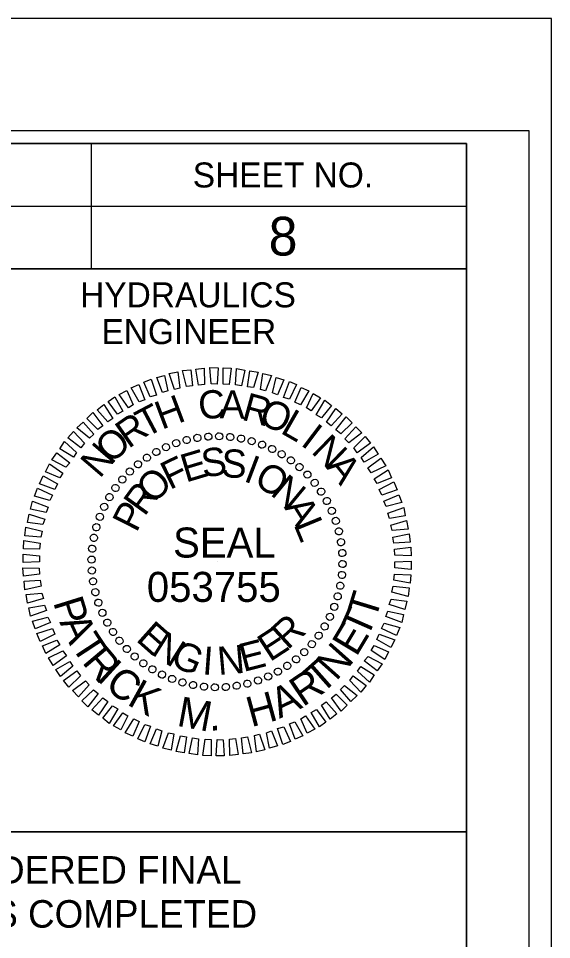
# Model space of a CAD drawing. Extents: x 1629887 to 1632095, y 1174261 to 1175361.
# Drawn here: x 1631464.8 to 1631571.3, y 1175176.7 to 1175360.8 of the extents above; entities that cross this region are included whole.
import ezdxf

# ---------------------------------------------------------------- set-up
doc = ezdxf.new("R2010")
doc.units = 0
for name, color, linetype in [('Sheet Data Field CELL', 7, 'Continuous'), ('Sheet PE Seal Cell', 7, 'Continuous'), ('Sheet Plot Border Inside CELL', 7, 'Continuous'), ('Sheet Plot Border Outside CELL', 7, 'Continuous'), ('Sheet Profile CELL', 7, 'Continuous'), ('Sheet Profile Grid Major CELL', 7, 'Continuous'), ('Sheet Sticker Exception Certification CELL', 7, 'Continuous')]:
    doc.layers.add(name, color=color, linetype=linetype)

msp = doc.modelspace()

# ---------------------------------------------------------------- linework, layer by layer
at = {"layer": 'Sheet PE Seal Cell'}
for p, q in [((1631500.58, 1175276.95), (1631500.58, 1175276.95)), ((1631502.73, 1175277.25), (1631502.73, 1175277.25)), ((1631504.93, 1175277.3), (1631504.93, 1175277.3)), ((1631507.13, 1175277.15), (1631507.13, 1175277.15)), ((1631509.28, 1175276.8), (1631509.28, 1175276.8)), ((1631494.28, 1175275.15), (1631494.28, 1175275.15)), ((1631496.28, 1175275.95), (1631496.28, 1175275.95)), ((1631498.38, 1175276.55), (1631498.38, 1175276.55)), ((1631511.38, 1175276.35), (1631511.38, 1175276.35)), ((1631513.48, 1175275.65), (1631513.48, 1175275.65)), ((1631492.33, 1175274.15), (1631492.33, 1175274.15)), ((1631515.48, 1175274.75), (1631515.48, 1175274.75)), ((1631517.43, 1175273.75), (1631517.43, 1175273.75)), ((1631488.68, 1175271.75), (1631488.68, 1175271.75)), ((1631490.43, 1175273), (1631490.43, 1175273)), ((1631519.23, 1175272.5), (1631519.23, 1175272.5)), ((1631487.03, 1175270.25), (1631487.03, 1175270.25)), ((1631520.98, 1175271.15), (1631520.98, 1175271.15)), ((1631522.53, 1175269.65), (1631522.53, 1175269.65)), ((1631485.53, 1175268.7), (1631485.53, 1175268.7)), ((1631524.03, 1175268), (1631524.03, 1175268)), ((1631484.18, 1175266.95), (1631484.18, 1175266.95)), ((1631525.28, 1175266.25), (1631525.28, 1175266.25)), ((1631482.93, 1175265.15), (1631482.93, 1175265.15)), ((1631526.43, 1175264.35), (1631526.43, 1175264.35)), ((1631481.93, 1175263.2), (1631481.93, 1175263.2)), ((1631527.43, 1175262.4), (1631527.43, 1175262.4)), ((1631481.03, 1175261.2), (1631481.03, 1175261.2)), ((1631528.23, 1175260.4), (1631528.23, 1175260.4)), ((1631480.33, 1175259.1), (1631480.33, 1175259.1)), ((1631479.88, 1175257), (1631479.88, 1175257)), ((1631528.83, 1175258.3), (1631528.83, 1175258.3)), ((1631479.53, 1175254.85), (1631479.53, 1175254.85)), ((1631529.23, 1175256.1), (1631529.23, 1175256.1)), ((1631529.53, 1175253.95), (1631529.53, 1175253.95)), ((1631479.38, 1175252.65), (1631479.38, 1175252.65)), ((1631504.48, 1175252.2), (1631504.48, 1175252.2)), ((1631529.58, 1175251.75), (1631529.58, 1175251.75)), ((1631479.43, 1175250.45), (1631479.43, 1175250.45)), ((1631529.43, 1175249.55), (1631529.43, 1175249.55)), ((1631479.73, 1175248.3), (1631479.73, 1175248.3)), ((1631529.08, 1175247.4), (1631529.08, 1175247.4)), ((1631480.13, 1175246.1), (1631480.13, 1175246.1)), ((1631480.73, 1175244), (1631480.73, 1175244)), ((1631528.63, 1175245.3), (1631528.63, 1175245.3)), ((1631481.53, 1175242), (1631481.53, 1175242)), ((1631527.93, 1175243.2), (1631527.93, 1175243.2)), ((1631482.53, 1175240.05), (1631482.53, 1175240.05)), ((1631527.03, 1175241.2), (1631527.03, 1175241.2)), ((1631483.68, 1175238.15), (1631483.68, 1175238.15)), ((1631526.03, 1175239.25), (1631526.03, 1175239.25)), ((1631484.93, 1175236.4), (1631484.93, 1175236.4)), ((1631524.78, 1175237.45), (1631524.78, 1175237.45)), ((1631486.43, 1175234.75), (1631486.43, 1175234.75)), ((1631523.43, 1175235.7), (1631523.43, 1175235.7)), ((1631487.98, 1175233.25), (1631487.98, 1175233.25)), ((1631520.28, 1175232.65), (1631520.28, 1175232.65)), ((1631521.93, 1175234.15), (1631521.93, 1175234.15)), ((1631489.73, 1175231.9), (1631489.73, 1175231.9)), ((1631518.53, 1175231.4), (1631518.53, 1175231.4)), ((1631491.53, 1175230.65), (1631491.53, 1175230.65)), ((1631493.48, 1175229.65), (1631493.48, 1175229.65)), ((1631514.68, 1175229.25), (1631514.68, 1175229.25)), ((1631516.63, 1175230.25), (1631516.63, 1175230.25)), ((1631495.48, 1175228.75), (1631495.48, 1175228.75)), ((1631497.58, 1175228.05), (1631497.58, 1175228.05)), ((1631499.68, 1175227.6), (1631499.68, 1175227.6)), ((1631501.83, 1175227.25), (1631501.83, 1175227.25)), ((1631504.03, 1175227.1), (1631504.03, 1175227.1)), ((1631506.23, 1175227.15), (1631506.23, 1175227.15)), ((1631508.38, 1175227.45), (1631508.38, 1175227.45)), ((1631510.58, 1175227.85), (1631510.58, 1175227.85)), ((1631512.68, 1175228.45), (1631512.68, 1175228.45))]:
    msp.add_line(p, q, dxfattribs=at)
for points in [[(1631495.98, 1175286.65), (1631494.93, 1175289.8), (1631496.63, 1175290.15), (1631497.03, 1175286.9)], [(1631498.38, 1175287.2), (1631497.58, 1175290.4), (1631499.23, 1175290.55), (1631499.58, 1175287.35)], [(1631500.78, 1175287.5), (1631500.23, 1175290.7), (1631501.93, 1175290.9), (1631501.98, 1175287.65)], [(1631503.28, 1175287.75), (1631503.03, 1175291), (1631504.68, 1175290.95), (1631504.48, 1175287.7)], [(1631505.68, 1175287.7), (1631505.68, 1175290.95), (1631507.33, 1175290.9), (1631506.88, 1175287.65)], [(1631508.18, 1175287.55), (1631508.38, 1175290.8), (1631510.03, 1175290.5), (1631509.38, 1175287.35)], [(1631510.58, 1175287.15), (1631511.03, 1175290.35), (1631512.68, 1175290.1), (1631511.78, 1175287)], [(1631513.13, 1175286.6), (1631513.63, 1175289.85), (1631515.33, 1175289.45), (1631514.18, 1175286.35)], [(1631491.13, 1175285.2), (1631489.83, 1175288.1), (1631491.33, 1175288.7), (1631492.38, 1175285.5)], [(1631493.58, 1175286), (1631492.43, 1175289), (1631493.98, 1175289.45), (1631494.63, 1175286.35)], [(1631515.53, 1175285.95), (1631516.28, 1175289.05), (1631517.83, 1175288.55), (1631516.58, 1175285.6)], [(1631517.78, 1175285.05), (1631518.93, 1175288.2), (1631520.33, 1175287.6), (1631518.93, 1175284.7)], [(1631486.78, 1175282.95), (1631484.93, 1175285.65), (1631486.48, 1175286.45), (1631487.73, 1175283.55)], [(1631488.93, 1175284.15), (1631487.33, 1175286.95), (1631488.88, 1175287.65), (1631490.03, 1175284.6)], [(1631520.03, 1175284.1), (1631521.28, 1175287.05), (1631522.83, 1175286.35), (1631521.13, 1175283.55)], [(1631484.58, 1175281.7), (1631482.73, 1175284.25), (1631484.03, 1175285.2), (1631485.68, 1175282.3)], [(1631522.33, 1175282.95), (1631523.68, 1175285.8), (1631525.18, 1175284.95), (1631523.28, 1175282.35)], [(1631524.28, 1175281.6), (1631526.03, 1175284.5), (1631527.33, 1175283.45), (1631525.38, 1175281)], [(1631482.68, 1175280.2), (1631480.53, 1175282.6), (1631481.88, 1175283.65), (1631483.63, 1175280.85)], [(1631526.33, 1175280.1), (1631528.18, 1175282.85), (1631529.48, 1175281.75), (1631527.28, 1175279.4)], [(1631480.68, 1175278.65), (1631478.48, 1175280.85), (1631479.68, 1175282.05), (1631481.63, 1175279.35)], [(1631528.23, 1175278.55), (1631530.28, 1175281.15), (1631531.48, 1175279.95), (1631529.18, 1175277.8)], [(1631479.03, 1175276.9), (1631476.48, 1175278.95), (1631477.73, 1175280.1), (1631479.83, 1175277.7)], [(1631530.03, 1175276.8), (1631532.18, 1175279.15), (1631533.38, 1175277.95), (1631530.78, 1175276)], [(1631477.28, 1175275), (1631474.68, 1175276.95), (1631475.78, 1175278.25), (1631477.98, 1175275.9)], [(1631531.78, 1175275), (1631534.08, 1175277.25), (1631535.13, 1175275.9), (1631532.48, 1175274)], [(1631475.78, 1175273.1), (1631473.08, 1175274.8), (1631474.03, 1175276.25), (1631476.43, 1175274.05)], [(1631533.28, 1175273.05), (1631535.73, 1175275.15), (1631536.68, 1175273.7), (1631533.88, 1175272.1)], [(1631474.28, 1175271.1), (1631471.48, 1175272.6), (1631472.48, 1175274), (1631475.08, 1175272)], [(1631473.08, 1175268.95), (1631470.23, 1175270.2), (1631470.98, 1175271.75), (1631473.68, 1175269.9)], [(1631534.58, 1175271), (1631537.23, 1175272.9), (1631538.18, 1175271.4), (1631535.28, 1175270)], [(1631535.88, 1175268.8), (1631538.68, 1175270.55), (1631539.33, 1175269), (1631536.48, 1175267.85)], [(1631472.08, 1175266.65), (1631468.98, 1175267.8), (1631469.73, 1175269.35), (1631472.58, 1175267.75)], [(1631536.88, 1175266.65), (1631539.83, 1175268.15), (1631540.48, 1175266.55), (1631537.38, 1175265.55)], [(1631471.08, 1175264.45), (1631467.98, 1175265.35), (1631468.63, 1175266.9), (1631471.63, 1175265.5)], [(1631470.33, 1175262.05), (1631467.23, 1175262.7), (1631467.58, 1175264.35), (1631470.73, 1175263.1)], [(1631537.78, 1175264.3), (1631540.83, 1175265.6), (1631541.38, 1175264.05), (1631538.28, 1175263.25)], [(1631538.58, 1175261.9), (1631541.78, 1175263.05), (1631542.08, 1175261.4), (1631538.93, 1175260.85)], [(1631469.68, 1175259.65), (1631466.58, 1175260.05), (1631466.93, 1175261.75), (1631470.08, 1175260.7)], [(1631539.18, 1175259.5), (1631542.33, 1175260.45), (1631542.63, 1175258.75), (1631539.48, 1175258.45)], [(1631469.28, 1175257.1), (1631466.08, 1175257.4), (1631466.28, 1175259.1), (1631469.53, 1175258.3)], [(1631539.63, 1175257.1), (1631542.88, 1175257.8), (1631543.03, 1175256.1), (1631539.83, 1175255.9)], [(1631469.03, 1175254.7), (1631465.78, 1175254.8), (1631465.88, 1175256.45), (1631469.13, 1175255.9)], [(1631539.93, 1175254.7), (1631543.18, 1175255.1), (1631543.28, 1175253.4), (1631540.03, 1175253.5)], [(1631468.98, 1175252.2), (1631465.73, 1175252.05), (1631465.73, 1175253.75), (1631468.98, 1175253.4)], [(1631469.03, 1175249.7), (1631465.78, 1175249.3), (1631465.68, 1175251), (1631468.93, 1175250.9)], [(1631539.98, 1175252.2), (1631543.23, 1175252.35), (1631543.23, 1175250.65), (1631539.98, 1175251)], [(1631539.93, 1175249.7), (1631543.18, 1175249.6), (1631543.08, 1175247.95), (1631539.83, 1175248.5)], [(1631469.33, 1175247.3), (1631466.08, 1175246.6), (1631465.93, 1175248.3), (1631469.13, 1175248.5)], [(1631469.78, 1175244.9), (1631466.63, 1175243.95), (1631466.33, 1175245.65), (1631469.48, 1175245.95)], [(1631539.68, 1175247.3), (1631542.88, 1175247), (1631542.68, 1175245.3), (1631539.43, 1175246.1)], [(1631539.28, 1175244.75), (1631542.38, 1175244.35), (1631542.03, 1175242.65), (1631538.88, 1175243.7)], [(1631470.38, 1175242.5), (1631467.18, 1175241.35), (1631466.88, 1175243), (1631470.03, 1175243.55)], [(1631538.63, 1175242.35), (1631541.73, 1175241.7), (1631541.38, 1175240.05), (1631538.23, 1175241.3)], [(1631471.18, 1175240.1), (1631468.13, 1175238.8), (1631467.58, 1175240.35), (1631470.68, 1175241.15)], [(1631472.08, 1175237.75), (1631469.13, 1175236.25), (1631468.48, 1175237.85), (1631471.58, 1175238.85)], [(1631537.88, 1175239.95), (1631540.98, 1175239.05), (1631540.33, 1175237.5), (1631537.33, 1175238.9)], [(1631473.08, 1175235.6), (1631470.28, 1175233.85), (1631469.63, 1175235.4), (1631472.48, 1175236.55)], [(1631536.88, 1175237.75), (1631539.98, 1175236.6), (1631539.23, 1175235.05), (1631536.38, 1175236.65)], [(1631535.88, 1175235.45), (1631538.73, 1175234.2), (1631537.98, 1175232.65), (1631535.28, 1175234.5)], [(1631474.38, 1175233.4), (1631471.73, 1175231.5), (1631470.78, 1175233), (1631473.68, 1175234.4)], [(1631534.68, 1175233.3), (1631537.48, 1175231.8), (1631536.48, 1175230.4), (1631533.88, 1175232.4)], [(1631475.68, 1175231.35), (1631473.23, 1175229.25), (1631472.28, 1175230.7), (1631475.08, 1175232.3)], [(1631533.18, 1175231.3), (1631535.88, 1175229.6), (1631534.93, 1175228.15), (1631532.53, 1175230.35)], [(1631477.18, 1175229.4), (1631474.88, 1175227.15), (1631473.83, 1175228.5), (1631476.48, 1175230.4)], [(1631531.68, 1175229.4), (1631534.28, 1175227.45), (1631533.18, 1175226.15), (1631530.98, 1175228.5)], [(1631478.93, 1175227.6), (1631476.78, 1175225.25), (1631475.58, 1175226.45), (1631478.18, 1175228.4)], [(1631529.93, 1175227.5), (1631532.48, 1175225.45), (1631531.23, 1175224.3), (1631529.13, 1175226.7)], [(1631480.73, 1175225.85), (1631478.68, 1175223.25), (1631477.48, 1175224.45), (1631479.78, 1175226.6)], [(1631528.28, 1175225.75), (1631530.48, 1175223.55), (1631529.28, 1175222.35), (1631527.33, 1175225.05)], [(1631482.63, 1175224.3), (1631480.78, 1175221.55), (1631479.48, 1175222.65), (1631481.68, 1175225)], [(1631484.68, 1175222.8), (1631482.93, 1175219.9), (1631481.63, 1175220.95), (1631483.58, 1175223.4)], [(1631526.28, 1175224.2), (1631528.43, 1175221.8), (1631527.08, 1175220.75), (1631525.33, 1175223.55)], [(1631486.63, 1175221.45), (1631485.28, 1175218.6), (1631483.78, 1175219.45), (1631485.68, 1175222.05)], [(1631524.38, 1175222.7), (1631526.23, 1175220.15), (1631524.93, 1175219.2), (1631523.28, 1175222.1)], [(1631488.93, 1175220.3), (1631487.68, 1175217.35), (1631486.13, 1175218.05), (1631487.83, 1175220.85)], [(1631520.03, 1175220.25), (1631521.63, 1175217.45), (1631520.08, 1175216.75), (1631518.93, 1175219.8)], [(1631522.18, 1175221.45), (1631524.03, 1175218.75), (1631522.48, 1175217.95), (1631521.23, 1175220.85)], [(1631491.18, 1175219.35), (1631490.03, 1175216.2), (1631488.63, 1175216.8), (1631490.03, 1175219.7)], [(1631493.43, 1175218.45), (1631492.68, 1175215.35), (1631491.13, 1175215.85), (1631492.38, 1175218.8)], [(1631495.83, 1175217.8), (1631495.33, 1175214.55), (1631493.63, 1175214.95), (1631494.78, 1175218.05)], [(1631515.38, 1175218.4), (1631516.53, 1175215.4), (1631514.98, 1175214.95), (1631514.33, 1175218.05)], [(1631517.83, 1175219.2), (1631519.13, 1175216.3), (1631517.63, 1175215.7), (1631516.58, 1175218.9)], [(1631498.38, 1175217.25), (1631497.93, 1175214.05), (1631496.28, 1175214.3), (1631497.18, 1175217.4)], [(1631500.78, 1175216.85), (1631500.58, 1175213.6), (1631498.93, 1175213.9), (1631499.58, 1175217.05)], [(1631503.28, 1175216.7), (1631503.28, 1175213.45), (1631501.63, 1175213.5), (1631502.08, 1175216.75)], [(1631505.68, 1175216.65), (1631505.93, 1175213.4), (1631504.28, 1175213.45), (1631504.48, 1175216.7)], [(1631508.18, 1175216.9), (1631508.73, 1175213.7), (1631507.03, 1175213.5), (1631506.98, 1175216.75)], [(1631510.58, 1175217.2), (1631511.38, 1175214), (1631509.73, 1175213.85), (1631509.38, 1175217.05)], [(1631512.98, 1175217.75), (1631514.03, 1175214.6), (1631512.33, 1175214.25), (1631511.93, 1175217.5)]]:
    msp.add_lwpolyline(points, close=True, dxfattribs=at)
for centre, major_axis in [((1631498.42, 1175276.53), (-0.174, 0.699)), ((1631500.56, 1175276.97), (-0.113, 0.711)), ((1631502.73, 1175277.22), (-0.05, 0.718)), ((1631504.92, 1175277.28), (0.013, 0.72)), ((1631507.11, 1175277.14), (0.075, 0.716)), ((1631509.27, 1175276.82), (0.137, 0.707)), ((1631511.4, 1175276.31), (0.198, 0.692)), ((1631492.33, 1175274.14), (-0.349, 0.63)), ((1631494.28, 1175275.11), (-0.293, 0.658)), ((1631496.32, 1175275.91), (-0.234, 0.681)), ((1631513.47, 1175275.61), (0.258, 0.672)), ((1631515.48, 1175274.74), (0.316, 0.647)), ((1631490.46, 1175272.99), (-0.403, 0.597)), ((1631517.4, 1175273.7), (0.371, 0.617)), ((1631519.23, 1175272.49), (0.423, 0.582)), ((1631488.7, 1175271.69), (-0.453, 0.56)), ((1631520.94, 1175271.13), (0.472, 0.543)), ((1631485.56, 1175268.65), (-0.543, 0.472)), ((1631487.06, 1175270.24), (-0.5, 0.518)), ((1631522.53, 1175269.62), (0.518, 0.5)), ((1631484.19, 1175266.94), (-0.582, 0.423)), ((1631523.98, 1175267.98), (0.56, 0.453)), ((1631482.99, 1175265.12), (-0.617, 0.371)), ((1631525.28, 1175266.22), (0.597, 0.403)), ((1631481.94, 1175263.19), (-0.647, 0.316)), ((1631526.42, 1175264.36), (0.63, 0.349)), ((1631527.4, 1175262.4), (0.658, 0.293)), ((1631481.07, 1175261.19), (-0.672, 0.258)), ((1631528.2, 1175260.37), (0.681, 0.234)), ((1631480.38, 1175259.11), (-0.692, 0.198)), ((1631528.82, 1175258.27), (0.699, 0.174)), ((1631479.87, 1175256.99), (-0.707, 0.137)), ((1631529.26, 1175256.12), (0.711, 0.113)), ((1631479.54, 1175254.82), (-0.716, 0.075)), ((1631529.5, 1175253.95), (0.718, 0.05)), ((1631479.41, 1175252.64), (-0.72, 0.013)), ((1631479.47, 1175250.45), (-0.718, -0.05)), ((1631529.56, 1175251.76), (0.72, -0.013)), ((1631529.43, 1175249.58), (0.716, -0.075)), ((1631479.71, 1175248.28), (-0.711, -0.113)), ((1631529.1, 1175247.41), (0.707, -0.137)), ((1631480.15, 1175246.13), (-0.699, -0.174)), ((1631528.59, 1175245.29), (0.692, -0.198)), ((1631480.77, 1175244.03), (-0.681, -0.234)), ((1631527.9, 1175243.21), (0.672, -0.258)), ((1631481.57, 1175242), (-0.658, -0.293)), ((1631527.03, 1175241.21), (0.647, -0.316)), ((1631482.55, 1175240.04), (-0.63, -0.349)), ((1631525.98, 1175239.28), (0.617, -0.371)), ((1631483.69, 1175238.18), (-0.597, -0.403)), ((1631524.77, 1175237.46), (0.582, -0.423)), ((1631484.99, 1175236.42), (-0.56, -0.453)), ((1631523.41, 1175235.75), (0.543, -0.472)), ((1631486.44, 1175234.78), (-0.518, -0.5)), ((1631521.91, 1175234.16), (0.5, -0.518)), ((1631488.03, 1175233.27), (-0.472, -0.543)), ((1631489.74, 1175231.91), (-0.423, -0.582)), ((1631520.27, 1175232.71), (0.453, -0.56)), ((1631491.57, 1175230.7), (-0.371, -0.617)), ((1631516.64, 1175230.26), (0.349, -0.63)), ((1631518.51, 1175231.41), (0.403, -0.597)), ((1631493.49, 1175229.66), (-0.316, -0.647)), ((1631495.5, 1175228.79), (-0.258, -0.672)), ((1631512.65, 1175228.49), (0.234, -0.681)), ((1631514.69, 1175229.29), (0.293, -0.658)), ((1631497.57, 1175228.09), (-0.198, -0.692)), ((1631499.7, 1175227.58), (-0.137, -0.707)), ((1631501.86, 1175227.26), (-0.075, -0.716)), ((1631504.05, 1175227.12), (-0.013, -0.72)), ((1631506.23, 1175227.18), (0.05, -0.718)), ((1631508.41, 1175227.43), (0.113, -0.711)), ((1631510.55, 1175227.86), (0.174, -0.699))]:
    msp.add_ellipse(centre, major_axis=major_axis, ratio=0.999708, dxfattribs=at)
at = {"layer": 'Sheet Plot Border Inside CELL'}
msp.add_lwpolyline([(1629900.31, 1174283.24), (1631566.81, 1174283.24), (1631566.81, 1175338.34), (1629900.31, 1175338.34)], close=True, dxfattribs=at)
at = {"layer": 'Sheet Plot Border Outside CELL'}
msp.add_lwpolyline([(1629887.31, 1174260.79), (1631571.31, 1174260.79), (1631571.31, 1175360.79), (1629887.31, 1175360.79)], close=True, dxfattribs=at)
at = {"layer": 'Sheet Profile CELL'}
for p, q in [((1631479.31, 1175335.74), (1631479.31, 1175310.74)), ((1631354.26, 1175323.24), (1631554.31, 1175323.24))]:
    msp.add_line(p, q, dxfattribs=at)
for points in [[(1631554.31, 1175335.79), (1630054.31, 1175335.79), (1630054.31, 1174285.79), (1631554.31, 1174285.79)], [(1631354.26, 1175335.79), (1631554.31, 1175335.79), (1631554.31, 1175310.74), (1631354.26, 1175310.74)], [(1631454.31, 1175310.74), (1631554.31, 1175310.74), (1631554.31, 1175198.24), (1631454.31, 1175198.24)]]:
    msp.add_lwpolyline(points, close=True, dxfattribs=at)
at = {"layer": 'Sheet Profile Grid Major CELL'}
msp.add_lwpolyline([(1631504.31, 1175174.74), (1631504.31, 1174835.79), (1631554.31, 1174835.79), (1631554.31, 1175185.79)], dxfattribs=at)
at = {"layer": 'Sheet Sticker Exception Certification CELL'}
for p, q in [((1631354.26, 1175198.24), (1631554.3, 1175198.24)), ((1631554.3, 1175198.22), (1631554.3, 1175174.72))]:
    msp.add_line(p, q, dxfattribs=at)

# ---------------------------------------------------------------- texts
at = {"layer": 'Sheet Data Field CELL'}
msp.add_text('8', height=7.75, dxfattribs=at).set_placement((1631514.79, 1175313.4))
at = {"layer": 'Sheet PE Seal Cell'}
for s, height, rotation, p in [('C', 5.64, 6.2199, (1631501.03, 1175280.55)), ('A', 5.64, 359.0203, (1631504.98, 1175280.85)), ('H', 5.64, 20.6195, (1631493.43, 1175278.55)), ('R', 5.64, 344.6211, (1631509.18, 1175280.65)), ('O', 5.64, 337.4212, (1631512.53, 1175279.9)), ('T', 5.64, 27.8198, (1631490.18, 1175276.9)), ('L', 5.64, 330.2209, (1631516.93, 1175278.05)), ('R', 5.64, 35.0205, (1631486.78, 1175274.7)), ('O', 5.64, 42.2217, (1631483.33, 1175271.6)), ('I', 5.64, 323.0201, (1631520.98, 1175275.65)), ('N', 5.64, 315.8189, (1631523.13, 1175274.1)), ('N', 5.64, 49.4235, (1631481.03, 1175268.7)), ('S', 5.64, 7.2556, (1631501.68, 1175269.05)), ('F', 5.64, 25.967, (1631495.03, 1175266.5)), ('E', 5.64, 16.6111, (1631498.23, 1175268)), ('S', 5.64, 357.9004, (1631505.28, 1175269.1)), ('I', 5.64, 339.1896, (1631509.58, 1175268.4)), ('O', 5.64, 329.8335, (1631511.58, 1175267.7)), ('A', 5.64, 308.6172, (1631526.08, 1175271.15)), ('O', 5.64, 44.6812, (1631491.73, 1175263.55)), ('N', 5.64, 320.4766, (1631514.93, 1175265.7)), ('R', 5.64, 54.0397, (1631489.98, 1175261.1)), ('P', 5.64, 63.3989, (1631488.38, 1175257.9)), ('A', 5.64, 301.7603, (1631517.78, 1175263.1)), ('L', 5.64, 292.4009, (1631519.73, 1175259.65)), ('SEAL', 5.998, 360, (1631495.69, 1175253.05)), ('T', 6, 72.9557, (1631536.09, 1175240.32)), ('P', 6, 287.3534, (1631471.69, 1175244.14)), ('T', 6, 66.1555, (1631534.46, 1175236.66)), ('A', 6, 294.4627, (1631472.94, 1175240.15)), ('E', 5.64, 318.2769, (1631488.08, 1175236.55)), ('R', 5.64, 42.4814, (1631518.58, 1175234.45)), ('E', 6, 59.0461, (1631532.31, 1175233.07)), ('T', 6, 303.303, (1631475.17, 1175235.44)), ('N', 5.64, 327.634, (1631491.08, 1175233.85)), ('E', 5.64, 33.1241, (1631515.03, 1175232.1)), ('E', 5.64, 14.4118, (1631509.73, 1175230.15)), ('R', 6, 310.1033, (1631477.36, 1175232.09)), ('G', 5.64, 336.9902, (1631494.88, 1175231.6)), ('I', 5.64, 355.7012, (1631501.43, 1175229.7)), ('N', 5.64, 5.0564, (1631504.78, 1175229.55)), ('N', 6, 48.3203, (1631528.26, 1175228.23)), ('I', 6, 317.5835, (1631480.21, 1175228.73)), ('T', 6, 41.5201, (1631525.26, 1175225.58)), ('C', 6, 321.3855, (1631481.82, 1175227.17)), ('R', 6, 34.0398, (1631521.62, 1175223.1)), ('K', 6, 330.9676, (1631486.3, 1175223.75)), ('A', 6, 25.1995, (1631516.94, 1175220.82)), ('H', 6, 15.2155, (1631511.31, 1175219.13)), ('M', 6, 349.4519, (1631496.26, 1175219.45)), ('.', 6, 0.9814, (1631502.97, 1175218.47))]:
    msp.add_text(s, height=height, rotation=rotation, dxfattribs=at).set_placement(p)
msp.add_text('053755', height=5.998, dxfattribs=at).set_placement((1631490.45, 1175244.19))
at = {"layer": 'Sheet Profile CELL'}
for s, p in [('SHEET NO.', (1631499.63, 1175327)), ('HYDRAULICS', (1631477.13, 1175303.05)), ('ENGINEER', (1631481.38, 1175295.7))]:
    msp.add_text(s, height=5, rotation=360, dxfattribs=at).set_placement(p)
at = {"layer": 'Sheet Sticker Exception Certification CELL'}
for s, p in [('DOCUMENT NOT CONSIDERED FINAL', (1631375.33, 1175187.89)), ('UNLESS ALL SIGNATURES COMPLETED', (1631370.26, 1175179.09))]:
    msp.add_text(s, height=5.5, rotation=360, dxfattribs=at).set_placement(p)

doc.saveas('drawing.dxf')
